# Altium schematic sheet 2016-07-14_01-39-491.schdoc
size 212 x 165 mm; SheetNumber: 1; SheetTotal: 1
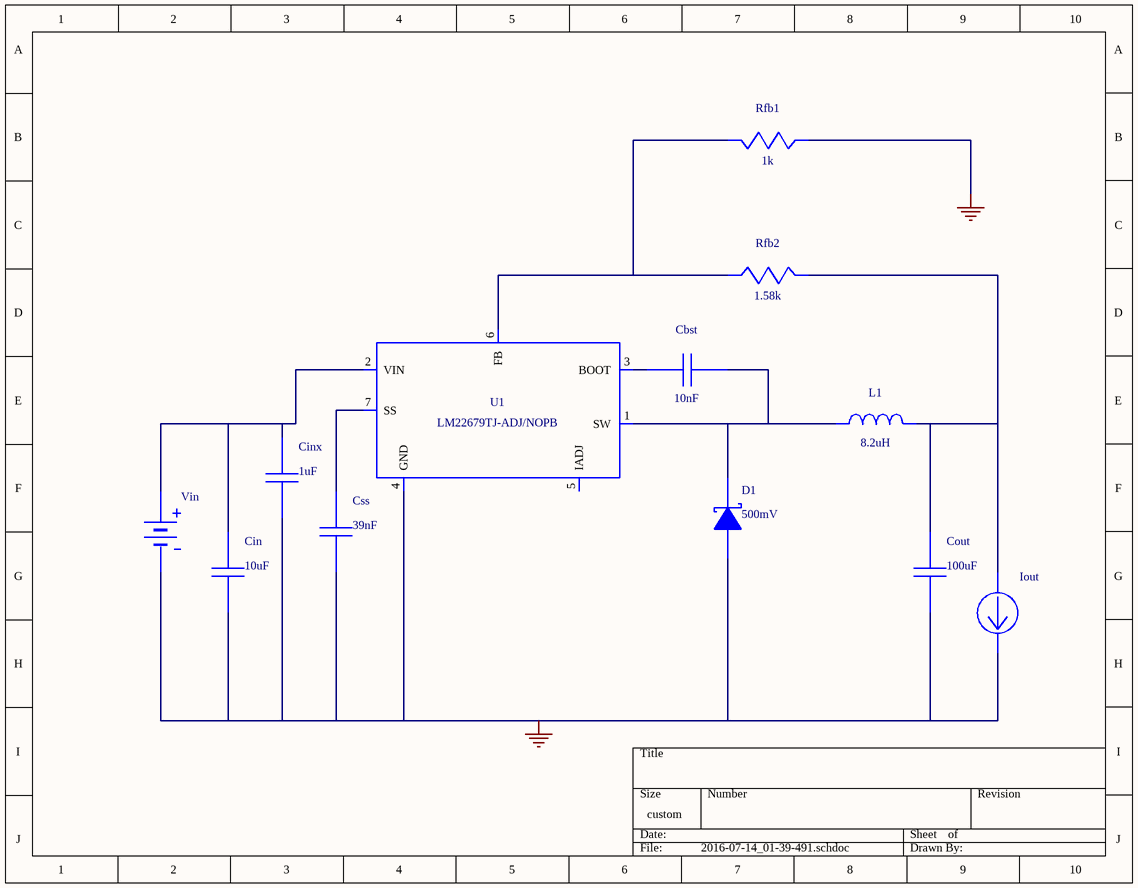
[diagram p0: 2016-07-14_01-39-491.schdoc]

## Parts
Cbst  value 10nF  (hidden comment: C0805C103K5RACTU)
Cin  value 10uF  (hidden comment: GRM32ER7YA106KA12L)
Cinx  value 1uF  (hidden comment: GMK212B7105KG-T)
Cout  value 100uF  (hidden comment: GRM31CR60J107ME39L)
Css  value 39nF  (hidden comment: 08055C393KAT2A)
D1  value 500mV  (hidden comment: B340A-13-F)
Iout  WB_CURRENT_LOAD  (value not drawn)
L1  value 8.2uH  (hidden comment: SRN8040-8R2Y)
Rfb1  value 1k  (hidden comment: ERJ-6ENF1001V)
Rfb2  value 1.58k  (hidden comment: ERJ-6ENF1581V)
U1  LM22679TJ-ADJ/NOPB
Vin  WB_BATTERY  (value not drawn)

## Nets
0: Cin.2 Cinx.2 Cout.2 Css.2 D1.2(A) Iout.2(-) Rfb1.2 U1.4(GND) U1.8(DAP) Vin.2(-)
NetCbst_1: Cbst.1 D1.1(K) L1.1 U1.1(SW)
NetCbst_2: Cbst.2 U1.3(BOOT)
NetCin_1: Cin.1 Cinx.1 U1.2(VIN) Vin.1(+)
NetCout_1: Cout.1 Iout.1(+) L1.2 Rfb2.1
NetCss_1: Css.1 U1.7(SS)
NetRfb1_1: Rfb1.1 Rfb2.2 U1.6(FB)

Not connected (* = marked no-connect by the designer): U1 5(IADJ)

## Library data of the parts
Cbst = C0805C103K5RACTU: Manufacturer Name: Kemet
Cin = GRM32ER7YA106KA12L: GRM32ER7YA106KA1; Manufacturer Name: MuRata
Cinx = GMK212B7105KG-T: Manufacturer Name: Taiyo Yuden
Cout = GRM31CR60J107ME39L: GRM31CR60J107ME3; Manufacturer Name: MuRata
Css = 08055C393KAT2A: Manufacturer Name: AVX
D1 = B340A-13-F: Manufacturer Name: Diodes Inc.
L1 = SRN8040-8R2Y: Manufacturer Name: Bourns
Rfb1 = ERJ-6ENF1001V: Manufacturer Name: Panasonic
Rfb2 = ERJ-6ENF1581V: Manufacturer Name: Panasonic
U1 = LM22679TJ-ADJ/NOPB: LM22679TJ-ADJ/NO; Manufacturer Name: Texas Instruments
